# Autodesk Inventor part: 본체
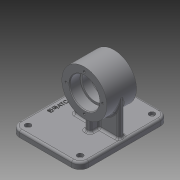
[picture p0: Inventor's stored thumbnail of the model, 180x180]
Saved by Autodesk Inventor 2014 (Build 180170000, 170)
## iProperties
Created: 2019-09
Part Number: 본체
Material: Generic
Document SubType Name: Modeling
Designer: kh
Density: 1 g/cm^3
Appearance: Default
Author: kh
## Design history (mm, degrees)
sketch "Sketch1"
  geometry: L1 (-63, -49)-(63, -49); L2 (63, -49)-(63, 49); L3 (63, 49)-(-63, 49); L4 (-63, 49)-(-63, -49); L5 (-63, -49)-(63, 49); L6 (63, -49)-(-63, 49); 1 further point
  constraints: 12 end point, 2 midpoint, 2 parallel, 1 horizontal, 1 perpendicular
  dimensions: "d0" = 126 distance of L2.end L3.end; "d1" = 98 distance of L1.end L2.end
extrude "Extrusion1" new body sketch "Sketch1" distance "d2" = 9; taper "d3" = 0 deg
fillet "Fillet1" dims "d4" = 12
sketch "Sketch2"
  geometry: A1 r 12 centre (-51, 37) between (-51, 49) and (-63, 37) reference; A2 r 12 centre (51, 37) between (63, 37) and (51, 49) reference; A3 r 12 centre (51, -37) between (51, -49) and (63, -37) reference; A4 r 12 centre (-51, -37) between (-63, -37) and (-51, -49) reference; 5 further points
  constraints: 4 coincident
hole "Hole1" sketch "Sketch2" at (-51, 37), (-51, -37), (51, -37), (51, 37) diameter "d5" = 4.5; stored, may be unused: countersink angle "d9" = 90 deg, drill point angle "d11" = 118 deg; dims "d6" = 6, "d7" = 8, "d8" = 4.4, "d10" = 8
workplane "Work Plane1"
sketch "Sketch5"
  geometry: L1 (0, 0)-(102, 0) reference; L2 (72, -59)-(30, -59); L3 (30, -59)-(30, -91); L4 (30, -91)-(72, -91); L5 (72, -91)-(72, -59); L6 (30, -80)-(45, -80); L7 (45, -80)-(45, -77); L8 (45, -77)-(57, -77); L9 (57, -77)-(57, -80); L10 (57, -80)-(72, -80); 3 further points
  constraints: 18 end point, 5 perpendicular, 4 parallel, 2 collinear, 2 midpoint, 2 point on line, 1 vertical alignment
  dimensions: "d14" = 42 distance of L2.start L2.end; "d15" = 59 distance from line of L1 L2.start; "d16" = 64 diameter of L4 L2; "d17" = 42 diameter of L6 L2; "d18" = 36 diameter of L8 L2; "d19" = 15 distance of L6.start L6.end
revolve "Revolution1" sketch "Sketch5" stored, may be unused: angle "d20" = 90 deg
sketch "Sketch6"
  geometry: C1 r 32 at (0, 0) reference; A1 r 26 centre (0, 0) between (-26, 0) and (0, -26); 3 further points
  constraints: 4 point on circle, 2 horizontal alignment, 2 vertical alignment, 1 centre point, 1 coincident
  dimensions: "d22" = 52 diameter of A1
hole "Hole2" sketch "Sketch6" at (-26, 0), (0, -26), (26, 0), (0, 26) diameter "d23" = 3.242; stored, may be unused: countersink angle "d27" = 90 deg, drill point angle "d29" = 118 deg; dims "d24" = 8, "d25" = 8, "d26" = 4.4, "d28" = 10
mirror "Mirror1"
sketch "Sketch9"
  geometry: L1 (21, -19)-(-21, -19) reference; L2 (21, 45)-(-21, 45) reference; L3 (51, 49)-(-51, 49) reference; L4 (-4, 45)-(-4, -19); L5 (4, 45)-(4, -19); L6 (4, -19)-(-4, -19); L7 (-4, 45)-(4, 45); L8 (0, 0)-(0, 18.132)
  constraints: 10 end point, 4 point on line, 3 perpendicular, 2 collinear, 1 other
  dimensions: "d30" = 8 distance of L5.end L4.end
extrude "Extrusion2" join sketch "Sketch9" stored distance "d31" = 6; taper "d32" = 0 deg
sketch "Sketch10"
  geometry: L1 (0, -9)-(102, -9) reference; L2 (51, 0)-(51, -22.25); L3 (34, -9)-(34, -22.25); L4 (68, -9)-(68, -22.25)
  constraints: 6 end point, 2 parallel, 2 point on line, 1 perpendicular, 1 other
  dimensions: "d34" = 34 distance of L4.start L3.start
feature "Rib1" dims "d35" = 1, "d36" = 8, "d37" = 0, "d38" = 0, "d39" = 1, "d40" = 1
feature "Rib2" dims "d41" = 1, "d42" = 8, "d43" = 0, "d44" = 0, "d45" = 1, "d46" = 1
fillet "Fillet2" dims "d47" = 0.3
chamfer "Chamfer1" distance "d48" = 1; stored, may be unused: second distance "d49" = 2, angle "d50" = 45 deg
fillet "Fillet3" dims "d51" = 3
fillet "Fillet4" dims "d52" = 3
sketch "Sketch11"
  geometry: L1 (-63, 37)-(-63, -37) reference; L2 (-51, -49)-(51, -49) reference; L3 (20.739, -42.002)-(-20.739, -42.002); L4 (-20.739, -42.002)-(-20.739, -35.998); L5 (-20.739, -35.998)-(20.739, -35.998); L6 (20.739, -35.998)-(20.739, -42.002); L7 (-20.739, -35.998)-(20.739, -42.002); L8 (20.739, -35.998)-(-20.739, -42.002); 2 further points
  constraints: 4 end point, 1 midpoint, 2 other
  dimensions: "d53" = 63 distance from line of L1 point (0, -39); "d54" = 10 distance from line of L2 point (0, -39)
emboss "Emboss1" sketch "Sketch11" dims "d55" = 0.5, "d56" = 0
body "Solid1"
other parameters: "d13" = -36
